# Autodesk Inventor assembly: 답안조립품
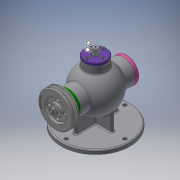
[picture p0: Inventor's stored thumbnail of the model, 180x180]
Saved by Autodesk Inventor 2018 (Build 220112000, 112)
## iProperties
Created: 2020-08
Part Number: 답안조립품
Material: 일반
Document SubType Name: Assembly
Designer: USER
Author: USER
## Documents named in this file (18)
- C:\Users\USER\Desktop\700806V1018\답안조립품.iam
- C:\Users\USER\Desktop\700806V1018\본체.ipt
- C:\Users\USER\Desktop\700806V1018\V-벨트풀리.ipt
- C:\Users\USER\Desktop\700806V1018\너트 M8.ipt
- C:\Users\USER\Desktop\700806V1018\뒤커버.ipt
- C:\Users\USER\Desktop\700806V1018\멈춤링 15x1.ipt
- C:\Users\USER\Desktop\700806V1018\멈춤링 35x1.6.ipt
- 멈춤링 35x1.6.ipt
- C:\Users\USER\Desktop\700806V1018\베어링 6202.ipt
- 베어링 6202.ipt
- C:\Users\USER\Desktop\700806V1018\볼트 M4.ipt
- C:\Users\USER\Desktop\700806V1018\상부커버.ipt
- C:\Users\USER\Desktop\700806V1018\슬라이드.ipt
- C:\Users\USER\Desktop\700806V1018\앞커버.ipt
- C:\Users\USER\Desktop\700806V1018\오일 실 15 30 7.ipt
- C:\Users\USER\Desktop\700806V1018\칼라.ipt
- C:\Users\USER\Desktop\700806V1018\키 3x3x12.ipt
- C:\Users\USER\Desktop\700806V1018\편심축.ipt
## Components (1 placed, 1 different names)
1. V-벨트풀리:1
